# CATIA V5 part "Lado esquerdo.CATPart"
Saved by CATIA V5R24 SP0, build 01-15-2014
Part number: Lado esquerdo
Bounding box of the stored display mesh (mm): x 0 to 3, y -198.5 to 198.5, z -225 to 225
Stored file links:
  C:\Users\Fatec\Desktop\Maquina componentes catia\Lado esquerdo.CATPart
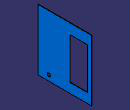
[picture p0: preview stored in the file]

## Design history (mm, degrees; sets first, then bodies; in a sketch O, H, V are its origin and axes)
Body1 (main body)
  Sketch1 on yz-plane, origin (0, 0, 0), H (0, 1, 0), V (0, 0, 1)
    line L1 (-198.5, 225) -> (198.5, 225)
    line L2 (198.5, 225) -> (198.5, -225)
    line L3 (198.5, -225) -> (-198.5, -225)
    line L4 (-198.5, -225) -> (-198.5, 225)
    length L4 = 450
    length L3 = 397
    horizontal: L1 H, L3 H
    vertical: L2 V, L4 V
    symmetry: L4 L2 V, L3 L1 H
  Pad1: profile Sketch1, direction (1, 0, 0), length 3
  Sketch2 on end face of Pad1, origin (3, 0, 0), H (0, 1, 0), V (0, 0, 1)
    reference projected line E1 (-198.5, -225) -> (198.5, -225) from edge [face of Pad1 from Sketch1.L3 | end face of Pad1]
    reference projected line E2 (-198.5, 225) -> (-198.5, -225) from edge [face of Pad1 from Sketch1.L4 | end face of Pad1]
    line L1 (38.5, 150) -> (168.5, 150)
    line L2 (168.5, 150) -> (168.5, -155)
    line L3 (168.5, -155) -> (38.5, -155)
    line L4 (38.5, -155) -> (38.5, 150)
    reference projected line E3 (198.5, -225) -> (198.5, 225) from edge [face of Pad1 from Sketch1.L2 | end face of Pad1]
    reference projected line E4 (198.5, 225) -> (-198.5, 225) from edge [face of Pad1 from Sketch1.L1 | end face of Pad1]
    line L5 (-128.5, -175) -> (-108.5, -175)
    line L6 (-108.5, -175) -> (-108.5, -195)
    line L7 (-108.5, -195) -> (-128.5, -195)
    line L8 (-128.5, -195) -> (-128.5, -175)
    length L3 = 130
    distance E1 L3 = 70
    distance E3 L2 = 30
    distance L1 E4 = 75
    length L8 = 20
    length L5 = 20
    distance L7 E1 = 30
    distance L8 E2 = 70
    horizontal: L1 H, L3 H, L5 H, L7 H
    vertical: L2 V, L4 V, L6 V, L8 V
  Pocket1: profile Sketch2, direction (-1, 0, 0), through (limit type 6)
